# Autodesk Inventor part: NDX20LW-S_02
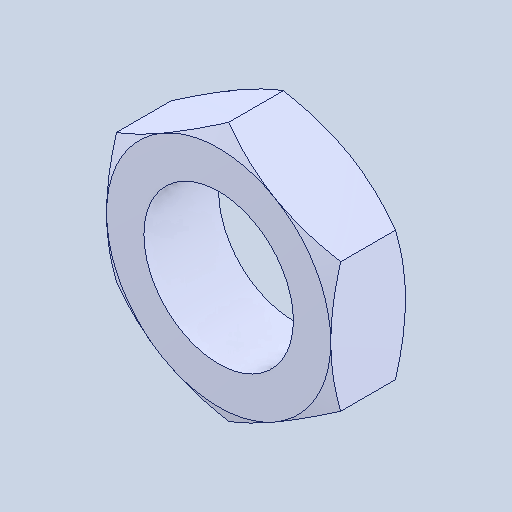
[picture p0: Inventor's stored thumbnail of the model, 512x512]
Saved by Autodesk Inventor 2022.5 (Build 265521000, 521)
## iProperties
Created: 2024-05
Part Number: NDX20LW-S_02
Material: 一般
Document SubType Name: Modeling
Designer: ImaoCorp
Density: 1 g/cm^3
Appearance: 既定
Author: ImaoCorp
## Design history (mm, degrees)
feature "NDX20LW-S_02"
node "ソリッド1"
